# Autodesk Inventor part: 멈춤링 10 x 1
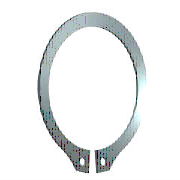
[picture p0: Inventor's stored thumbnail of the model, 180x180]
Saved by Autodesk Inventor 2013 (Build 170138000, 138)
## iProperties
IsCustomPart: 0
Company: 한국ATC센터
Created: 2009-02
Part Number: 멈춤링 10 x 1
Material: Steel, Mild
Description: 리테이닝 링(C형)
Document SubType Name: Modeling
Standard: KS B 1336
Designer: KYOUNG IL JANG
Standards Organization: KS
Language: ko-KR
Size Designation: 10 x 1
Categories: <MemberInstance><Categories><Category DisplayName="샤프트 부품" InternalName="7f7aeb1f-a693-4053-b835-cee3144e0d98" Mnemonic="SHFT"><Category DisplayName="써클립" Inter
Density: 7.86 g/cm^3
Mass: 0.423089 g
Surface Area: 1.9243 cm^2
Volume: 0.0538281 cm^3
Author: KYOUNG IL JANG
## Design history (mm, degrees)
sketch "스케치1"
  geometry: L1 (-6, 0)-(6, 0) reference; L2 (0, 20.189)-(0, -80.536) reference; L3 (-48.09, 0)-(48.09, 0) reference; L4 (-0.3, -9.791)-(-0.3, -12.791); L5 (-0.3, -6.54)-(-0.3, -13.29); L6 (-2.795, 1.6)-(3.672, 1.6); L7 (0.3, -6.54)-(0.3, -13.29); L8 (0.3, -9.791)-(0.3, -12.791); C1 r 0.6 at (-1.2, -11.486); C2 r 0.6 at (1.2, -11.486); A1 r 4.8 centre (0, -5) between (0.3, -9.791) and (-0.3, -9.791); A2 r 6.2 centre (0, -4.6) between (2.988, -10.033) and (-2.988, -10.033); A3 r 7.796 centre (0, -5) between (-1.418, -12.666) and (-0.3, -12.791); A4 r 1.2 centre (-1.2, -11.486) between (-2.383, -11.285) and (-1.418, -12.666); A5 r 1.2 centre (-3.566, -11.084) between (-2.383, -11.285) and (-2.988, -10.033); A6 r 1.2 centre (3.566, -11.084) between (2.988, -10.033) and (2.383, -11.285); A7 r 1.2 centre (1.2, -11.486) between (1.418, -12.666) and (2.383, -11.285); A8 r 7.796 centre (0, -5) between (0.3, -12.791) and (1.418, -12.666)
  constraints: 16 point on circle, 12 end point, 10 centre point, 9 symmetric about line, 5 point on line, 4 tangent, 3 coincident, 2 horizontal, 1 perpendicular, 1 vertical, 5 other
  dimensions: "d0" = 9.6 diameter of A1 (= ND); "d1" = 3 distance of L4.end L4.start (= SRB2); "d6" = 0.3 distance between parallel lines of L2 L5 (= 0.25 x SD5); "d7" = 1.6 distance between parallel lines of L6 L3 (= SRB1); "d8" = 0.4 distance of A1.centre A2.centre (= 0.25 x SRB1); "d9" = 1.2 radius of A4 (= SD5); "d10" = 1.2 radius of A5 (= SD5); "d11" = 0.9 distance from line of L4 A4.centre (= 0.75 x SD5); "d12" = 1.2 diameter of C1 (= SD5); "d13" = 1.2 diameter of C2 (= SD5); "d14" = 5 distance from line of A1.centre L1 (= 0.5 x WD)
extrude "본체" new body sketch "스케치1" distance "d2" = 1 (= SD); taper "d3" = 0 deg
workaxis "Work Axis1"
workplane "Work Plane1"
body "Solid1"
other parameters: "SD" = 1 [user parameter; used in 1 equation term], "SRB1" = 1.6 [user parameter; used in 2 equation terms], "ND" = 9.6 [user parameter; used in 1 equation term], "SRB2" = 3 [user parameter; used in 1 equation term], "SD5" = 1.2 [user parameter; used in 6 equation terms], "d15" = 0, "d16" = 0, "d17" = 0, "d41" = 0, "d42" = 0, "SD3" = 9.3 [user parameter], "WDMAX" = 11 [user parameter]
